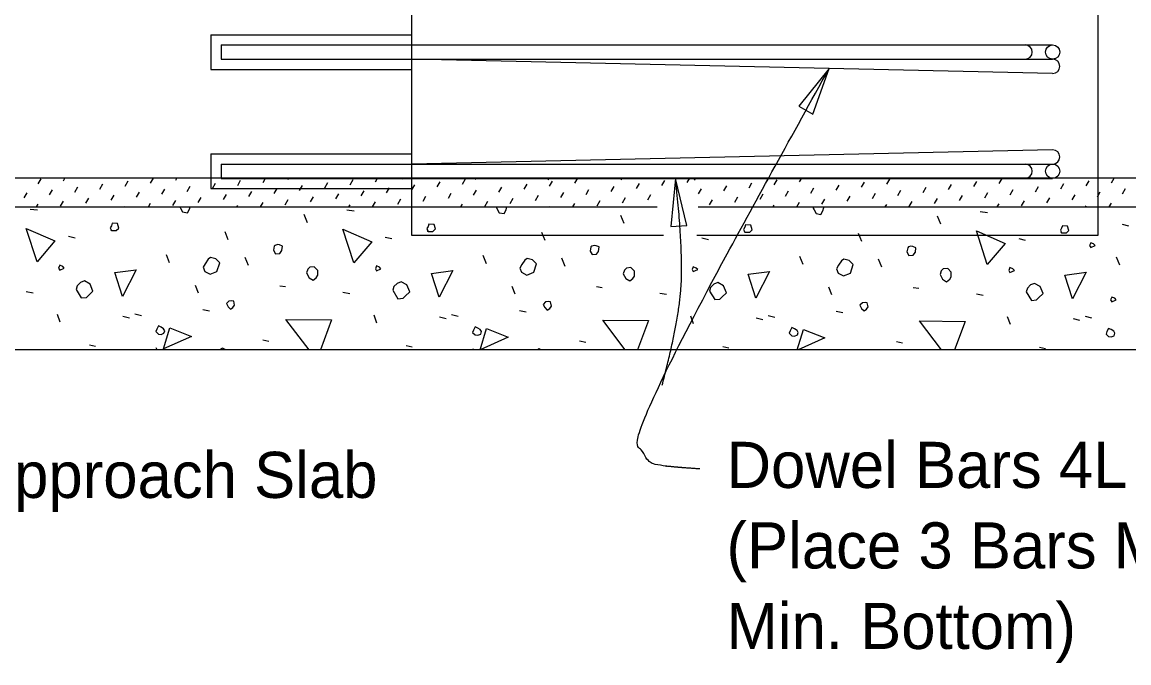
# Model space of a CAD drawing. Extents: x 21587 to 21659.1, y 56113.9 to 56155.9.
# Drawn here: x 21619.146 to 21623.985, y 56131.933 to 56134.734 of the extents above; entities that cross this region are included whole.
import ezdxf

# ---------------------------------------------------------------- set-up
doc = ezdxf.new("R2010")
doc.units = 0
for name, color, linetype in [('AdhocPoint_dp', 7, 'Continuous'), ('PlotBorder_dp', 7, 'Continuous'), ('SheetBorder_dp', 7, 'Continuous'), ('SheetLines_dp', 7, 'Continuous'), ('SubStrConc', 7, 'Continuous'), ('SubStrConc_h', 7, 'Continuous'), ('TextMisc', 7, 'Continuous')]:
    doc.layers.add(name, color=color, linetype=linetype)

msp = doc.modelspace()

# ---------------------------------------------------------------- linework, layer by layer
at = {"layer": 'AdhocPoint_dp'}
for p, q in [((21619.9721, 56134.6787), (21619.9721, 56134.5273)), ((21619.9721, 56134.6787), (21620.8499, 56134.6787)), ((21619.9721, 56134.5273), (21620.8499, 56134.5273)), ((21619.9721, 56134.1579), (21620.8499, 56134.1579)), ((21619.9721, 56134.1579), (21619.9721, 56134.0065)), ((21624.3563, 56134.0511), (21613.608, 56134.0511)), ((21619.9721, 56134.0065), (21620.8499, 56134.0065)), ((21613.608, 56133.926), (21621.9231, 56133.926)), ((21622.1027, 56133.926), (21624.3563, 56133.926)), ((21624.3563, 56133.301), (21618.8279, 56133.301))]:
    msp.add_line(p, q, dxfattribs=at)
at = {"layer": 'PlotBorder_dp'}
for points in [[(21622.6748, 56134.5311), (21622.5424, 56134.3666), (21622.604, 56134.3322)], [(21622.0034, 56134.0509), (21621.9823, 56133.8408), (21622.0527, 56133.8455)]]:
    msp.add_lwpolyline(points, close=True, dxfattribs=at)
for points in [[(21622.109, 56132.7809), (21621.9358, 56132.7915), (21621.8722, 56132.8163), (21621.805, 56132.9754), (21622.6748, 56134.5311)], [(21621.9446, 56133.1469), (21622.0135, 56133.4067), (21622.0391, 56133.7156), (21622.0034, 56134.0509)]]:
    msp.add_open_spline(points, degree=2, dxfattribs=at)
at = {"layer": 'SheetLines_dp'}
for p, q in [((21620.0165, 56134.6343), (21623.652, 56134.6343)), ((21620.0165, 56134.6343), (21620.0165, 56134.5718)), ((21620.0165, 56134.5718), (21623.652, 56134.5718)), ((21623.652, 56134.5094), (21620.8499, 56134.5718)), ((21623.652, 56134.1758), (21620.8499, 56134.1134)), ((21620.0165, 56134.1134), (21623.652, 56134.1134)), ((21620.0165, 56134.1134), (21620.0165, 56134.0509)), ((21620.0165, 56134.0509), (21623.652, 56134.0509))]:
    msp.add_line(p, q, dxfattribs=at)
for centre in [(21623.652, 56134.603), (21623.652, 56134.0822)]:
    msp.add_circle(centre, 0.0312, dxfattribs=at)
for centre in [(21623.5317, 56134.603), (21623.652, 56134.5406), (21623.652, 56134.5406), (21623.652, 56134.1446), (21623.5317, 56134.0822)]:
    msp.add_arc(centre, 0.0312, 270, 90, dxfattribs=at)
at = {"layer": 'SubStrConc'}
for p, q in [((21620.8499, 56134.0509), (21620.8499, 56134.8009)), ((21623.8499, 56134.8009), (21623.8499, 56134.0509))]:
    msp.add_line(p, q, dxfattribs=at)
at = {"layer": 'SubStrConc_h'}
for points in [[(21621.9508, 56133.8009), (21620.8499, 56133.8009), (21620.8499, 56134.0509)], [(21623.8499, 56134.0509), (21623.8499, 56133.8009), (21622.0964, 56133.8009)]]:
    msp.add_lwpolyline(points, dxfattribs=at)
at = {"layer": 'TextMisc'}
for p, q in [((21619.2168, 56134.0271), (21619.2298, 56134.0495)), ((21619.3275, 56134.04), (21619.3339, 56134.0511)), ((21619.3763, 56133.9912), (21619.3893, 56134.0136)), ((21619.4869, 56134.0042), (21619.4999, 56134.0266)), ((21619.5976, 56134.0171), (21619.6105, 56134.0395)), ((21619.7082, 56134.0301), (21619.7204, 56134.0511)), ((21619.8188, 56134.0431), (21619.8235, 56134.0511)), ((21619.8677, 56133.9942), (21619.8806, 56134.0166)), ((21619.9783, 56134.0072), (21619.9913, 56134.0296)), ((21620.0889, 56134.0202), (21620.1019, 56134.0426)), ((21620.1692, 56134.0497), (21620.1699, 56134.0509)), ((21620.1996, 56134.0331), (21620.21, 56134.0511)), ((21620.3102, 56134.0461), (21620.3131, 56134.0511)), ((21620.359, 56133.9973), (21620.372, 56134.0196)), ((21620.4697, 56134.0102), (21620.4826, 56134.0326)), ((21620.4886, 56134.0485), (21620.49, 56134.0509)), ((21620.5803, 56134.0232), (21620.5933, 56134.0456)), ((21620.6909, 56134.0361), (21620.6996, 56134.0511)), ((21620.8016, 56134.0491), (21620.8027, 56134.0511)), ((21620.808, 56134.0474), (21620.81, 56134.0509)), ((21620.8504, 56134.0003), (21620.8634, 56134.0227)), ((21620.961, 56134.0132), (21620.974, 56134.0356)), ((21621.0717, 56134.0262), (21621.0846, 56134.0486)), ((21621.1274, 56134.0462), (21621.1301, 56134.0509)), ((21621.2311, 56133.9903), (21621.2441, 56134.0127)), ((21621.3418, 56134.0033), (21621.3547, 56134.0257)), ((21621.4468, 56134.045), (21621.4502, 56134.0509)), ((21621.4524, 56134.0163), (21621.4654, 56134.0386)), ((21621.563, 56134.0292), (21621.5757, 56134.0511)), ((21621.7225, 56133.9933), (21621.7355, 56134.0157)), ((21621.7661, 56134.0438), (21621.7702, 56134.0509)), ((21621.8331, 56134.0063), (21621.8461, 56134.0287)), ((21621.9438, 56134.0193), (21621.9567, 56134.0417)), ((21622.0544, 56134.0322), (21622.0653, 56134.0511)), ((21622.0855, 56134.0426), (21622.0903, 56134.0509)), ((21622.2139, 56133.9964), (21622.2268, 56134.0188)), ((21622.3245, 56134.0093), (21622.3375, 56134.0317)), ((21622.4049, 56134.0415), (21622.4103, 56134.0509)), ((21622.4351, 56134.0223), (21622.4481, 56134.0447)), ((21622.5458, 56134.0353), (21622.5549, 56134.0511)), ((21622.7052, 56133.9994), (21622.7182, 56134.0218)), ((21622.8159, 56134.0124), (21622.8288, 56134.0347)), ((21622.9265, 56134.0253), (21622.9395, 56134.0477)), ((21623.086, 56133.9894), (21623.0989, 56134.0118)), ((21623.1966, 56134.0024), (21623.2096, 56134.0248)), ((21623.3072, 56134.0154), (21623.3202, 56134.0378)), ((21623.4179, 56134.0283), (21623.4308, 56134.0507)), ((21623.5773, 56133.9925), (21623.5903, 56134.0149)), ((21623.688, 56134.0054), (21623.7009, 56134.0278)), ((21623.7986, 56134.0184), (21623.8116, 56134.0408)), ((21623.9092, 56134.0314), (21623.9206, 56134.0511)), ((21619.155, 56133.9653), (21619.168, 56133.9877)), ((21619.2657, 56133.9782), (21619.2786, 56134.0006)), ((21619.4251, 56133.9424), (21619.4381, 56133.9648)), ((21619.5358, 56133.9553), (21619.5487, 56133.9777)), ((21619.6464, 56133.9683), (21619.6594, 56133.9907)), ((21619.757, 56133.9813), (21619.77, 56134.0037)), ((21619.9165, 56133.9454), (21619.9295, 56133.9678)), ((21620.0271, 56133.9584), (21620.0401, 56133.9808)), ((21620.1378, 56133.9713), (21620.1507, 56133.9937)), ((21620.2484, 56133.9843), (21620.2614, 56134.0067)), ((21620.4079, 56133.9484), (21620.4208, 56133.9708)), ((21620.5185, 56133.9614), (21620.5315, 56133.9838)), ((21620.6291, 56133.9743), (21620.6421, 56133.9967)), ((21620.7398, 56133.9873), (21620.7527, 56134.0097)), ((21620.8992, 56133.9514), (21620.9122, 56133.9738)), ((21621.0099, 56133.9644), (21621.0228, 56133.9868)), ((21621.1205, 56133.9774), (21621.1335, 56133.9998)), ((21621.28, 56133.9415), (21621.2929, 56133.9639)), ((21621.3906, 56133.9545), (21621.4036, 56133.9768)), ((21621.5012, 56133.9674), (21621.5142, 56133.9898)), ((21621.6119, 56133.9804), (21621.6248, 56134.0028)), ((21621.7713, 56133.9445), (21621.7843, 56133.9669)), ((21621.882, 56133.9575), (21621.8949, 56133.9799)), ((21622.1032, 56133.9834), (21622.1162, 56134.0058)), ((21622.2627, 56133.9475), (21622.2757, 56133.9699)), ((21622.3733, 56133.9605), (21622.3863, 56133.9829)), ((21622.484, 56133.9735), (21622.4969, 56133.9959)), ((21622.5946, 56133.9864), (21622.6076, 56134.0088)), ((21622.7541, 56133.9506), (21622.767, 56133.9729)), ((21622.8647, 56133.9635), (21622.8777, 56133.9859)), ((21622.9753, 56133.9765), (21622.9883, 56133.9989)), ((21623.1348, 56133.9406), (21623.1478, 56133.963)), ((21623.2454, 56133.9536), (21623.2584, 56133.976)), ((21623.3561, 56133.9665), (21623.369, 56133.9889)), ((21623.4667, 56133.9795), (21623.4797, 56134.0019)), ((21623.6262, 56133.9436), (21623.6391, 56133.966)), ((21623.7368, 56133.9566), (21623.7498, 56133.979)), ((21623.8474, 56133.9696), (21623.8604, 56133.9919)), ((21623.9571, 56133.9838), (21623.97, 56134.0062)), ((21619.1816, 56133.9165), (21619.2134, 56133.913)), ((21619.2094, 56133.926), (21619.2168, 56133.9388)), ((21619.3145, 56133.9294), (21619.3275, 56133.9518)), ((21619.5959, 56133.926), (21619.5976, 56133.9289)), ((21619.699, 56133.926), (21619.7082, 56133.9419)), ((21619.8059, 56133.9324), (21619.8188, 56133.9548)), ((21620.0855, 56133.926), (21620.0889, 56133.9319)), ((21620.1886, 56133.926), (21620.1996, 56133.9449)), ((21620.2972, 56133.9355), (21620.3102, 56133.9578)), ((21620.5751, 56133.926), (21620.5803, 56133.9349)), ((21620.6783, 56133.926), (21620.6909, 56133.9479)), ((21620.7886, 56133.9385), (21620.8016, 56133.9609)), ((21621.0648, 56133.926), (21621.0717, 56133.938)), ((21621.1693, 56133.9285), (21621.1823, 56133.9509)), ((21621.4512, 56133.926), (21621.4524, 56133.928)), ((21621.5544, 56133.926), (21621.563, 56133.941)), ((21621.6607, 56133.9315), (21621.6737, 56133.9539)), ((21622.1521, 56133.9346), (21622.165, 56133.957)), ((21622.4305, 56133.926), (21622.4351, 56133.9341)), ((21622.5336, 56133.926), (21622.5458, 56133.947)), ((21622.6434, 56133.9376), (21622.6564, 56133.96)), ((21622.9201, 56133.926), (21622.9265, 56133.9371)), ((21623.0242, 56133.9276), (21623.0371, 56133.95)), ((21623.3066, 56133.926), (21623.3072, 56133.9271)), ((21623.4097, 56133.926), (21623.4179, 56133.9401)), ((21623.5155, 56133.9307), (21623.5285, 56133.9531)), ((21623.7962, 56133.926), (21623.7986, 56133.9302)), ((21623.8993, 56133.926), (21623.9092, 56133.9431)), ((21620.3937, 56133.857), (21620.3795, 56133.8924)), ((21620.5663, 56133.913), (21620.5981, 56133.9094)), ((21621.7784, 56133.8535), (21621.7642, 56133.8889)), ((21623.163, 56133.85), (21623.1489, 56133.8853)), ((21623.3356, 56133.9059), (21623.3675, 56133.9024)), ((21620.0478, 56133.7822), (21620.0337, 56133.8175)), ((21623.9556, 56133.8507), (21623.9839, 56133.8437)), ((21619.3496, 56133.7981), (21619.3778, 56133.791)), ((21620.7342, 56133.7945), (21620.7625, 56133.7875)), ((21621.4325, 56133.7786), (21621.4184, 56133.814)), ((21622.1189, 56133.791), (21622.1472, 56133.7839)), ((21622.8172, 56133.7751), (21622.803, 56133.8104)), ((21623.5036, 56133.7875), (21623.5319, 56133.7804)), ((21619.7915, 56133.6814), (21619.7774, 56133.7168)), ((21620.1356, 56133.6697), (21620.1214, 56133.705)), ((21621.1762, 56133.6779), (21621.162, 56133.7132)), ((21621.5203, 56133.6661), (21621.5061, 56133.7015)), ((21622.5609, 56133.6743), (21622.5467, 56133.7097)), ((21622.9049, 56133.6626), (21622.8908, 56133.6979)), ((21623.9455, 56133.6708), (21623.9314, 56133.7062)), ((21619.917, 56133.5488), (21619.9046, 56133.5824)), ((21620.2735, 56133.5813), (21620.2982, 56133.5777)), ((21621.3017, 56133.5453), (21621.2893, 56133.5789)), ((21621.6581, 56133.5777), (21621.6829, 56133.5742)), ((21622.6864, 56133.5417), (21622.674, 56133.5753)), ((21619.1646, 56133.5565), (21619.1946, 56133.5512)), ((21620.5492, 56133.553), (21620.5793, 56133.5477)), ((21621.9339, 56133.5494), (21621.964, 56133.5441)), ((21623.0428, 56133.5742), (21623.0676, 56133.5707)), ((21623.3186, 56133.5459), (21623.3486, 56133.5406)), ((21619.3131, 56133.4222), (21619.3007, 56133.4558)), ((21619.5871, 56133.4487), (21619.6153, 56133.4416)), ((21619.6395, 56133.4587), (21619.6678, 56133.4516)), ((21619.9358, 56133.477), (21619.9659, 56133.4717)), ((21620.6977, 56133.4186), (21620.6854, 56133.4522)), ((21620.9717, 56133.4451), (21621, 56133.4381)), ((21621.0241, 56133.4551), (21621.0524, 56133.4481)), ((21621.3205, 56133.4734), (21621.3506, 56133.4681)), ((21622.0824, 56133.4151), (21622.07, 56133.4487)), ((21622.3564, 56133.4416), (21622.3847, 56133.4345)), ((21622.4088, 56133.4516), (21622.4371, 56133.4445)), ((21622.7052, 56133.4699), (21622.7352, 56133.4646)), ((21623.4671, 56133.4116), (21623.4547, 56133.4451)), ((21623.7411, 56133.4381), (21623.7694, 56133.431)), ((21623.7935, 56133.4481), (21623.8218, 56133.441)), ((21620.1992, 56133.3444), (21620.2257, 56133.3391)), ((21621.5839, 56133.3408), (21621.6104, 56133.3355)), ((21622.9686, 56133.3373), (21622.9951, 56133.332)), ((21619.4403, 56133.3232), (21619.4669, 56133.3179)), ((21619.7364, 56133.301), (21619.7332, 56133.3097)), ((21620.825, 56133.3196), (21620.8515, 56133.3143)), ((21621.1197, 56133.301), (21621.1178, 56133.3061)), ((21622.2097, 56133.3161), (21622.2362, 56133.3108)), ((21622.5031, 56133.301), (21622.5025, 56133.3026)), ((21623.5944, 56133.3126), (21623.6209, 56133.3073))]:
    msp.add_line(p, q, dxfattribs=at)
for points in [[(21619.8362, 56133.926), (21619.8392, 56133.9201)], [(21619.8392, 56133.9201), (21619.8481, 56133.9041), (21619.8693, 56133.9006), (21619.8781, 56133.9165), (21619.8805, 56133.926)], [(21621.2212, 56133.926), (21621.2204, 56133.9236), (21621.2239, 56133.9165)], [(21621.2239, 56133.9165), (21621.2327, 56133.9006), (21621.254, 56133.8971), (21621.2628, 56133.913), (21621.2661, 56133.926)], [(21622.607, 56133.926), (21622.605, 56133.9201), (21622.6086, 56133.913)], [(21622.6086, 56133.913), (21622.6174, 56133.8971), (21622.6386, 56133.8935), (21622.6475, 56133.9094), (21622.651, 56133.9236), (21622.6486, 56133.926)], [(21619.2123, 56133.6856), (21619.1646, 56133.8323), (21619.2901, 56133.7775), (21619.2123, 56133.6856)], [(21619.5369, 56133.8228), (21619.5582, 56133.8228), (21619.5688, 56133.8334), (21619.5635, 56133.8529), (21619.5405, 56133.8546), (21619.5369, 56133.844), (21619.5316, 56133.8352), (21619.5369, 56133.8228), (21619.5334, 56133.8264)], [(21620.597, 56133.682), (21620.5492, 56133.8288), (21620.6748, 56133.774), (21620.597, 56133.682)], [(21620.9216, 56133.8193), (21620.9428, 56133.8193), (21620.9534, 56133.8299), (21620.9481, 56133.8493), (21620.9252, 56133.8511), (21620.9216, 56133.8405), (21620.9163, 56133.8317), (21620.9216, 56133.8193), (21620.9181, 56133.8228)], [(21622.3063, 56133.8158), (21622.3275, 56133.8158), (21622.3381, 56133.8264), (21622.3328, 56133.8458), (21622.3098, 56133.8476), (21622.3063, 56133.837), (21622.301, 56133.8281), (21622.3063, 56133.8158), (21622.3028, 56133.8193)], [(21623.3663, 56133.675), (21623.3186, 56133.8217), (21623.4441, 56133.7669), (21623.3663, 56133.675)], [(21623.691, 56133.8122), (21623.7122, 56133.8122), (21623.7228, 56133.8228), (21623.7175, 56133.8423), (21623.6945, 56133.844), (21623.691, 56133.8334), (21623.6857, 56133.8246), (21623.691, 56133.8122), (21623.6874, 56133.8158)], [(21623.8185, 56133.7486), (21623.8379, 56133.7574), (21623.8308, 56133.7645), (21623.8185, 56133.7698), (21623.8132, 56133.7574), (21623.8185, 56133.7486)], [(21620.2452, 56133.7368), (21620.254, 56133.7209), (21620.2735, 56133.7227), (21620.2823, 56133.7351), (21620.2841, 56133.7545), (21620.2717, 56133.7598), (21620.2629, 56133.7616), (21620.2523, 56133.758), (21620.2487, 56133.7545), (21620.2452, 56133.7368)], [(21621.6299, 56133.7333), (21621.6387, 56133.7174), (21621.6581, 56133.7192), (21621.667, 56133.7315), (21621.6688, 56133.751), (21621.6564, 56133.7563), (21621.6475, 56133.758), (21621.6369, 56133.7545), (21621.6334, 56133.751), (21621.6299, 56133.7333)], [(21623.0145, 56133.7298), (21623.0234, 56133.7138), (21623.0428, 56133.7156), (21623.0517, 56133.728), (21623.0534, 56133.7474), (21623.0411, 56133.7527), (21623.0322, 56133.7545), (21623.0216, 56133.751), (21623.0181, 56133.7474), (21623.0145, 56133.7298)], [(21619.9453, 56133.6443), (21619.9683, 56133.6319), (21619.9983, 56133.6443), (21620.0107, 56133.6814), (21619.993, 56133.6991), (21619.97, 56133.7044), (21619.9594, 56133.6973), (21619.9471, 56133.6779), (21619.9382, 56133.662), (21619.9453, 56133.6443)], [(21621.33, 56133.6407), (21621.353, 56133.6284), (21621.383, 56133.6407), (21621.3954, 56133.6779), (21621.3777, 56133.6955), (21621.3547, 56133.7008), (21621.3441, 56133.6938), (21621.3317, 56133.6743), (21621.3229, 56133.6584), (21621.33, 56133.6407)], [(21622.7146, 56133.6372), (21622.7376, 56133.6248), (21622.7677, 56133.6372), (21622.7801, 56133.6743), (21622.7624, 56133.692), (21622.7394, 56133.6973), (21622.7288, 56133.6902), (21622.7164, 56133.6708), (21622.7076, 56133.6549), (21622.7146, 56133.6372)], [(21619.3113, 56133.6502), (21619.3307, 56133.659), (21619.3237, 56133.6661), (21619.3113, 56133.6714), (21619.306, 56133.659), (21619.3113, 56133.6502)], [(21619.5847, 56133.5347), (21619.5511, 56133.639), (21619.6448, 56133.6514), (21619.5847, 56133.5347)], [(21620.3901, 56133.6378), (21620.4008, 56133.6166), (21620.4184, 56133.606), (21620.4326, 56133.6166), (21620.4396, 56133.6272), (21620.4396, 56133.6484), (21620.4237, 56133.6644), (21620.4043, 56133.6626), (21620.3954, 56133.6537), (21620.3901, 56133.6378)], [(21620.696, 56133.6467), (21620.7154, 56133.6555), (21620.7083, 56133.6626), (21620.696, 56133.6679), (21620.6907, 56133.6555), (21620.696, 56133.6467)], [(21620.9693, 56133.5311), (21620.9358, 56133.6354), (21621.0294, 56133.6478), (21620.9693, 56133.5311)], [(21621.7748, 56133.6343), (21621.7854, 56133.6131), (21621.8031, 56133.6025), (21621.8172, 56133.6131), (21621.8243, 56133.6237), (21621.8243, 56133.6449), (21621.8084, 56133.6608), (21621.789, 56133.659), (21621.7801, 56133.6502), (21621.7748, 56133.6343)], [(21622.0806, 56133.6431), (21622.1001, 56133.652), (21622.093, 56133.659), (21622.0806, 56133.6644), (21622.0753, 56133.652), (21622.0806, 56133.6431)], [(21622.354, 56133.5276), (21622.3204, 56133.6319), (21622.4141, 56133.6443), (21622.354, 56133.5276)], [(21623.1595, 56133.6308), (21623.1701, 56133.6096), (21623.1878, 56133.5989), (21623.2019, 56133.6096), (21623.209, 56133.6202), (21623.209, 56133.6414), (21623.1931, 56133.6573), (21623.1736, 56133.6555), (21623.1648, 56133.6467), (21623.1595, 56133.6308)], [(21623.4653, 56133.6396), (21623.4848, 56133.6484), (21623.4777, 56133.6555), (21623.4653, 56133.6608), (21623.46, 56133.6484), (21623.4653, 56133.6396)], [(21623.7387, 56133.5241), (21623.7051, 56133.6284), (21623.7988, 56133.6407), (21623.7387, 56133.5241)], [(21619.382, 56133.5654), (21619.405, 56133.5282), (21619.428, 56133.53), (21619.4368, 56133.5388), (21619.4562, 56133.5583), (21619.4439, 56133.5883), (21619.4191, 56133.6025), (21619.4014, 56133.5954), (21619.3873, 56133.5813), (21619.382, 56133.5654)], [(21620.7667, 56133.5618), (21620.7897, 56133.5247), (21620.8126, 56133.5265), (21620.8215, 56133.5353), (21620.8409, 56133.5547), (21620.8285, 56133.5848), (21620.8038, 56133.5989), (21620.7861, 56133.5919), (21620.772, 56133.5777), (21620.7667, 56133.5618)], [(21622.1514, 56133.5583), (21622.1743, 56133.5212), (21622.1973, 56133.5229), (21622.2062, 56133.5318), (21622.2256, 56133.5512), (21622.2132, 56133.5813), (21622.1885, 56133.5954), (21622.1708, 56133.5883), (21622.1567, 56133.5742), (21622.1514, 56133.5583)], [(21623.536, 56133.5547), (21623.559, 56133.5176), (21623.582, 56133.5194), (21623.5908, 56133.5282), (21623.6103, 56133.5477), (21623.5979, 56133.5777), (21623.5732, 56133.5919), (21623.5555, 56133.5848), (21623.5413, 56133.5707), (21623.536, 56133.5547)], [(21623.9109, 56133.5108), (21623.9303, 56133.5197), (21623.9232, 56133.5267), (21623.9109, 56133.5321), (21623.9056, 56133.5197), (21623.9109, 56133.5108)], [(21620.0472, 56133.4893), (21620.0578, 56133.4787), (21620.0684, 56133.4858), (21620.0755, 56133.4964), (21620.0719, 56133.5141), (21620.0631, 56133.5159), (21620.0507, 56133.5141), (21620.0401, 56133.5035), (21620.0472, 56133.4893)], [(21621.4319, 56133.4858), (21621.4425, 56133.4752), (21621.4531, 56133.4823), (21621.4602, 56133.4929), (21621.4566, 56133.5106), (21621.4478, 56133.5123), (21621.4354, 56133.5106), (21621.4248, 56133.4999), (21621.4319, 56133.4858)], [(21622.8166, 56133.4823), (21622.8272, 56133.4717), (21622.8378, 56133.4787), (21622.8448, 56133.4893), (21622.8413, 56133.507), (21622.8325, 56133.5088), (21622.8201, 56133.507), (21622.8095, 56133.4964), (21622.8166, 56133.4823)], [(21620.4015, 56133.301), (21620.3, 56133.4345), (21620.4997, 56133.4328), (21620.4505, 56133.301)], [(21621.7835, 56133.301), (21621.6847, 56133.431), (21621.8844, 56133.4292), (21621.8365, 56133.301)], [(21619.742, 56133.3703), (21619.7544, 56133.3685), (21619.7667, 56133.3738), (21619.7703, 56133.3844), (21619.765, 56133.3933), (21619.7544, 56133.4003), (21619.742, 56133.4056), (21619.7349, 56133.3915), (21619.7314, 56133.3809), (21619.742, 56133.3703)], [(21619.7644, 56133.3055), (21619.7926, 56133.3974), (21619.8863, 56133.3603), (21619.7644, 56133.3055)], [(21621.1267, 56133.3667), (21621.1391, 56133.365), (21621.1514, 56133.3703), (21621.155, 56133.3809), (21621.1497, 56133.3897), (21621.1391, 56133.3968), (21621.1267, 56133.4021), (21621.1196, 56133.388), (21621.1161, 56133.3773), (21621.1267, 56133.3667)], [(21621.149, 56133.302), (21621.1773, 56133.3939), (21621.271, 56133.3568), (21621.149, 56133.302)], [(21622.5114, 56133.3632), (21622.5237, 56133.3614), (21622.5361, 56133.3667), (21622.5396, 56133.3773), (21622.5343, 56133.3862), (21622.5237, 56133.3933), (21622.5114, 56133.3986), (21622.5043, 56133.3844), (21622.5007, 56133.3738), (21622.5114, 56133.3632)], [(21622.5345, 56133.301), (21622.562, 56133.3903), (21622.6557, 56133.3532), (21622.5394, 56133.301)], [(21623.1655, 56133.301), (21623.0693, 56133.4275), (21623.2691, 56133.4257), (21623.2225, 56133.301)], [(21623.896, 56133.3597), (21623.9084, 56133.3579), (21623.9208, 56133.3632), (21623.9243, 56133.3738), (21623.919, 56133.3827), (21623.9084, 56133.3897), (21623.896, 56133.395), (21623.889, 56133.3809), (21623.8854, 56133.3703), (21623.896, 56133.3597)], [(21620.0368, 56133.301), (21620.0366, 56133.302), (21620.0224, 56133.309), (21620.009, 56133.301)], [(21621.4161, 56133.301), (21621.4071, 56133.3055), (21621.3996, 56133.301)], [(21622.7937, 56133.301), (21622.7918, 56133.302), (21622.7902, 56133.301)]]:
    msp.add_lwpolyline(points, dxfattribs=at)

# ---------------------------------------------------------------- texts
at = {"layer": 'PlotBorder_dp'}
for s, p in [('Dowel Bars 4L (10" Embedment) ', (21622.226, 56132.6977)), ('(Place 3 Bars Min. Top and 1 Bar ', (21622.226, 56132.3457)), ('Min. Bottom)', (21622.226, 56131.9937))]:
    msp.add_text(s, height=0.2016, dxfattribs=at).set_placement(p)
at = {"layer": 'SheetBorder_dp'}
msp.add_text('Existing Approach Slab', height=0.2016, dxfattribs=at).set_placement((21617.9127, 56132.654))

doc.saveas('drawing.dxf')
